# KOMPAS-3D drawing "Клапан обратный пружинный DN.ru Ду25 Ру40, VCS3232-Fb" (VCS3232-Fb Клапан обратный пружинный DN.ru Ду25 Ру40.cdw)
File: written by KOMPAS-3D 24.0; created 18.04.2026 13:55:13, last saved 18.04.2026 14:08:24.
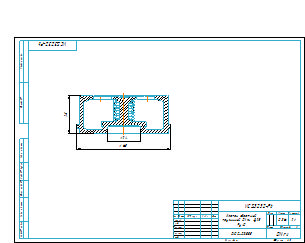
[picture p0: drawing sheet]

Document properties: c3d_UniqueCompID: 071bd168-1a06-425c-849c-e99e84a96128; Наименование: Деталь; Автор: 712; Класс точности: c; Знак неуказанной шероховатости: Шероховатость не задана; Рассекать на разрезах: Да; c3d_UniqueCompID: 071bd168-1a06-425c-849c-e99e84a96128; Наименование: Деталь; Автор: 712; Класс точности: c; Знак неуказанной шероховатости: Шероховатость не задана; Рассекать на разрезах: Да; c3d_UniqueCompID: 071bd168-1a06-425c-849c-e99e84a96128; Наименование: Деталь; Автор: 712; Класс точности: c; Знак неуказанной шероховатости: Шероховатость не задана; Рассекать на разрезах: Да; Автор: 712; Форматы листов документа: A3; Полное имя файла: VCS3232-Fb Клапан обратный пружинный DN.ru Ду25 Ру40.m3d; Масса: 0.36; Наименование: Клапан обратный пружинный DN.ru Ду25 Ру40; Количество листов документа: 1; Примечание: D100-03888

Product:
- Component: Пружина 1086-0796 ГОСТ 18793-80  | qty 1  | additional columns: 3953604318-4147491677-0; Деталь; Пользователь Windows; c; Шероховатость не задана; Да; Сталь 10  ГОСТ 1050-88; source file: Деталь.m3d
- Body: Тело 1  | qty 1
    Масса: 0.271999
- Part/product: Клапан обратный пружинный DN.ru Ду25 Ру40  | designation VCS3232-Fb
    Масса: 0.36
    Раздел спецификации: Прочие изделия
    Примечание: D100-03888
    additional columns: 071bd168-1a06-425c-849c-e99e84a96128; Деталь; 712; c; Шероховатость не задана; Да

Views: Вид 1, Местный разрез 1, Спереди
Referenced files in C:\Users\712\Desktop\Новая папка (4)\: VCS3232-Fb Клапан обратный пружинный DN.ru Ду15 Ру40.m3d, VCS3232-Fb Клапан обратный пружинный DN.ru Ду25 Ру40.m3d, VCS3232-Fb Клапан обратный пружинный DN.ru Ду15 Ру40.cdw
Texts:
  VCS3232-Fb
  Клапан обратный
  пружинный DN.ru Ду25
  Ру40
  Клапан обратный пружинный DN.ru Ду25 Ру40
  VCS3232-Fb Клапан обратный пружинный DN.ru Ду25 Ру40
Dimensions and other numbers on the sheet: 0; 3; 2; 4; 68; 24; 28; 7; 2:1; 1; 0,36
